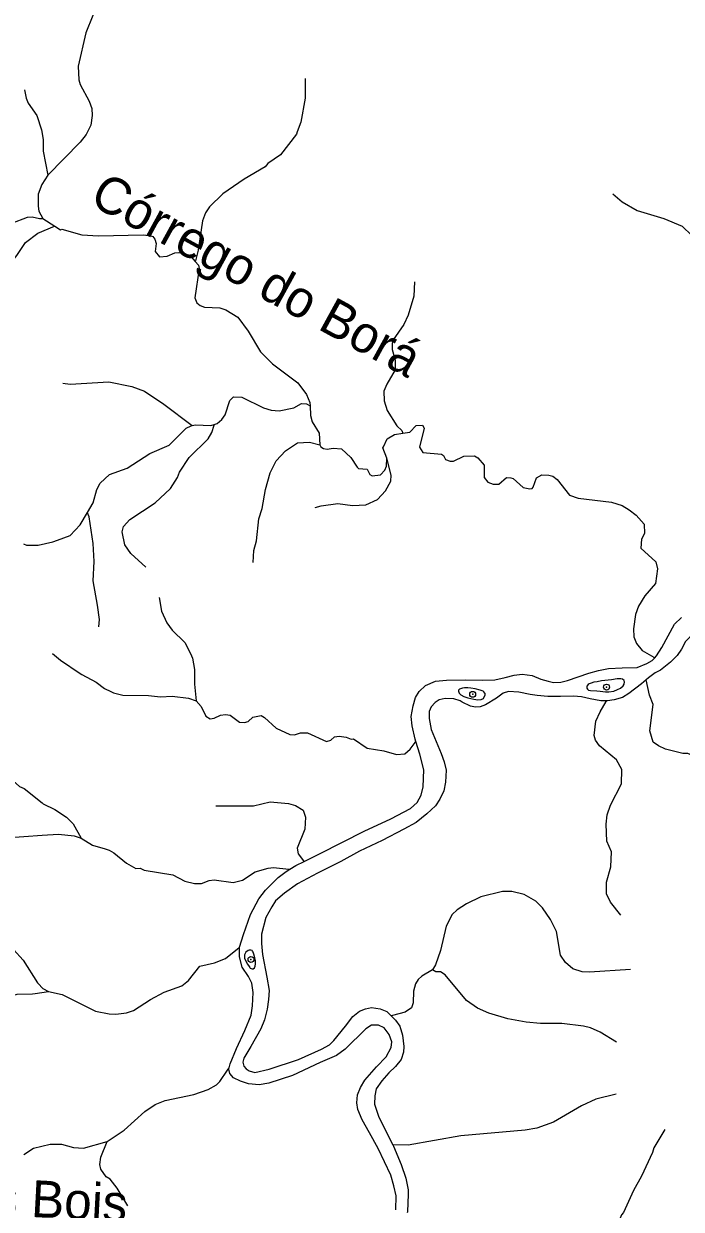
# Model space of a CAD drawing. Extents: x 393 to 446.6, y 8175.5 to 8231.
# Drawn here: x 402.2 to 405.77, y 8215.62 to 8222.05 of the extents above; entities that cross this region are included whole.
import ezdxf
from ezdxf.enums import TextEntityAlignment as Align

# ---------------------------------------------------------------- set-up
doc = ezdxf.new("R2010")
doc.units = 0
doc.header["$LTSCALE"] = 0.064
doc.header["$PDMODE"] = 32
doc.header["$PDSIZE"] = 0.032
doc.linetypes.add('LONG_DASHED', pattern=[7.5, 6, -1.5])
for name, color, linetype, lineweight in [('2', 7, 'Continuous', 25), ('7', 7, 'Continuous', 25), ('9', 7, 'LONG_DASHED', 25)]:
    doc.layers.add(name, color=color, linetype=linetype, lineweight=lineweight)
doc.layers.add('54', color=7, linetype='Continuous')
doc.layers.add('61', color=7, linetype='Continuous')

msp = doc.modelspace()

# ---------------------------------------------------------------- linework, layer by layer
at = {"layer": '2'}
for points in [[(406.6734, 8219.1519), (406.6511, 8219.1412), (406.5802, 8219.1176), (406.4922, 8219.0961), (406.3805, 8219.066), (406.2709, 8219.0252), (406.1979, 8218.9844), (406.142, 8218.9522), (406.1012, 8218.9135), (406.0132, 8218.8169), (405.9767, 8218.7846), (405.9358, 8218.7675), (405.895, 8218.7524), (405.8499, 8218.7417), (405.8156, 8218.7223), (405.7919, 8218.6987), (405.7705, 8218.6579), (405.7468, 8218.6235), (405.7103, 8218.587), (405.6566, 8218.5441), (405.6265, 8218.529), (405.59, 8218.5011), (405.5782, 8218.4907)], [(405.6244, 8218.6109), (405.6342, 8218.6216), (405.6635, 8218.6665), (405.7319, 8218.7934), (405.769, 8218.8285)], [(404.3299, 8218.1566), (404.3261, 8218.1686), (404.3105, 8218.2408), (404.3046, 8218.2916), (404.3144, 8218.3502), (404.3281, 8218.3951), (404.3476, 8218.4283), (404.3827, 8218.4595), (404.4354, 8218.483), (404.496, 8218.4888), (404.5994, 8218.4908), (404.6932, 8218.4888), (404.7576, 8218.4908), (404.8142, 8218.5044), (404.863, 8218.5161), (404.906, 8218.522), (404.9606, 8218.5142), (405.0075, 8218.4947), (405.0466, 8218.483), (405.0758, 8218.4771), (405.1149, 8218.479), (405.152, 8218.4869), (405.2672, 8218.5279), (405.3199, 8218.5415), (405.3746, 8218.5532), (405.4488, 8218.5552), (405.5288, 8218.5571), (405.5815, 8218.5786), (405.6108, 8218.5962), (405.6244, 8218.6109)], [(405.5782, 8218.4907), (405.5535, 8218.4689), (405.4848, 8218.4173), (405.4504, 8218.3959), (405.4053, 8218.383), (405.3688, 8218.3765), (405.3645, 8218.3765)], [(405.3645, 8218.3765), (405.3323, 8218.3765), (405.2743, 8218.3873), (405.227, 8218.398), (405.1841, 8218.4023), (405.1132, 8218.4002), (405.0445, 8218.4002), (404.9865, 8218.4066), (404.9499, 8218.4109), (404.8877, 8218.4238), (404.8318, 8218.4281), (404.8039, 8218.4195), (404.7674, 8218.3916), (404.7072, 8218.3551), (404.6793, 8218.3443), (404.6535, 8218.3422), (404.6256, 8218.3486), (404.5805, 8218.3701), (404.5698, 8218.3765), (404.5354, 8218.3873), (404.4881, 8218.3894), (404.4559, 8218.383), (404.4344, 8218.3679), (404.413, 8218.3443), (404.4022, 8218.3185), (404.4022, 8218.282), (404.413, 8218.2219), (404.4667, 8218.0909), (404.4838, 8218.0458), (404.4946, 8218.0006), (404.4903, 8217.9362), (404.4817, 8217.889), (404.4602, 8217.8438), (404.4366, 8217.8073), (404.3893, 8217.7644), (404.3313, 8217.7171), (404.2648, 8217.6806), (404.1466, 8217.6205), (404.0242, 8217.5625), (403.9232, 8217.5066), (403.7965, 8217.4422), (403.6891, 8217.3842), (403.6182, 8217.3348), (403.5688, 8217.2918), (403.5495, 8217.2596), (403.5173, 8217.2016), (403.4936, 8217.1114), (403.4936, 8217.062), (403.4979, 8217.0019), (403.5216, 8216.8794), (403.5345, 8216.8064), (403.5302, 8216.757), (403.5237, 8216.7054), (403.5087, 8216.6474), (403.4894, 8216.598), (403.4357, 8216.5035), (403.397, 8216.4391), (403.3927, 8216.4176), (403.397, 8216.3961), (403.4099, 8216.3811), (403.4271, 8216.3704), (403.4571, 8216.3618), (403.5345, 8216.379), (403.6934, 8216.4327), (403.818, 8216.4885), (403.8609, 8216.5121), (403.8846, 8216.5358), (403.949, 8216.6131), (403.9877, 8216.6646), (404.0242, 8216.6947), (404.0564, 8216.7076), (404.0886, 8216.714), (404.1359, 8216.7076), (404.1724, 8216.6926), (404.1959, 8216.6691)], [(403.7243, 8217.5059), (403.8107, 8217.5497), (404.0489, 8217.6707), (404.1933, 8217.7371), (404.3007, 8217.7937), (404.3378, 8217.825), (404.3593, 8217.866), (404.3691, 8217.9109), (404.373, 8218.0026), (404.3515, 8218.0886), (404.3299, 8218.1566)], [(403.6463, 8217.4634), (403.6798, 8217.4833), (403.7243, 8217.5059)], [(403.3747, 8217.0409), (403.3948, 8217.1104), (403.4338, 8217.2178), (403.4787, 8217.3037), (403.5139, 8217.3505), (403.5842, 8217.4189), (403.6271, 8217.4521), (403.6463, 8217.4634)], [(403.3179, 8216.3861), (403.3225, 8216.4094), (403.3577, 8216.4915), (403.4026, 8216.5891), (403.4377, 8216.673), (403.4436, 8216.7238), (403.4475, 8216.796), (403.4416, 8216.8468), (403.4221, 8216.8819), (403.3889, 8216.9327), (403.3733, 8216.9893), (403.3733, 8217.0362), (403.3747, 8217.0409)], [(404.1959, 8216.6691), (404.2196, 8216.6453), (404.2433, 8216.6131), (404.2583, 8216.5637), (404.2648, 8216.5035), (404.2626, 8216.4713), (404.2497, 8216.4327), (404.2196, 8216.394), (404.1831, 8216.3596), (404.1445, 8216.3167), (404.1144, 8216.2737), (404.108, 8216.235), (404.1058, 8216.1899), (404.1294, 8216.1191), (404.2055, 8215.969)], [(404.2207, 8215.6168), (404.2226, 8215.6929), (404.2109, 8215.7476), (404.1933, 8215.8042), (404.125, 8215.9487), (404.0781, 8216.0346), (404.0391, 8216.1049), (404.0157, 8216.1615), (404.0098, 8216.1966), (404.0137, 8216.2396), (404.0293, 8216.2806), (404.0528, 8216.3196), (404.1172, 8216.3919), (404.168, 8216.4465), (404.1953, 8216.4973), (404.1992, 8216.5285), (404.1855, 8216.5676), (404.1582, 8216.6047), (404.1269, 8216.6184), (404.0899, 8216.6184), (404.0586, 8216.5988), (403.9473, 8216.4875), (403.9005, 8216.4544), (403.8107, 8216.4153), (403.6603, 8216.345), (403.5334, 8216.304), (403.4807, 8216.2943), (403.4221, 8216.3001), (403.3792, 8216.3138), (403.3421, 8216.3333), (403.3206, 8216.3567), (403.3167, 8216.3802), (403.3179, 8216.3861)], [(404.2055, 8215.969), (404.2089, 8215.9623), (404.2497, 8215.8635), (404.2755, 8215.7883), (404.2884, 8215.726), (404.2884, 8215.7024), (404.2841, 8215.6057), (404.2836, 8215.6014)]]:
    msp.add_lwpolyline(points, dxfattribs=at)
for points in [[(405.2565, 8218.4569), (405.2559, 8218.4466), (405.2596, 8218.4411), (405.2656, 8218.435), (405.276, 8218.4326), (405.31, 8218.4308), (405.3288, 8218.4289), (405.3586, 8218.4253), (405.3762, 8218.4253), (405.4024, 8218.4302), (405.423, 8218.4387), (405.4388, 8218.4466), (405.4534, 8218.4581), (405.4589, 8218.4666), (405.4601, 8218.4806), (405.4592, 8218.4836), (405.4583, 8218.4867), (405.4504, 8218.4952), (405.4401, 8218.497), (405.4212, 8218.4964), (405.3908, 8218.4909), (405.3367, 8218.4848), (405.3118, 8218.4806), (405.2948, 8218.4776), (405.2802, 8218.4733), (405.2699, 8218.469), (405.2632, 8218.4648)], [(404.5614, 8218.4355), (404.5603, 8218.4297), (404.5646, 8218.4192), (404.5745, 8218.4102), (404.5898, 8218.4013), (404.6108, 8218.3934), (404.6276, 8218.3892), (404.6434, 8218.3855), (404.666, 8218.3829), (404.6844, 8218.3834), (404.697, 8218.3903), (404.7054, 8218.4087), (404.7049, 8218.4171), (404.7038, 8218.4192), (404.6991, 8218.425), (404.6938, 8218.4286), (404.6786, 8218.4344), (404.6518, 8218.4418), (404.6287, 8218.446), (404.6113, 8218.447), (404.5929, 8218.4475), (404.5819, 8218.4454), (404.5714, 8218.4428), (404.5656, 8218.4395)], [(403.4176, 8216.9487), (403.4255, 8216.9365), (403.4291, 8216.9316), (403.4322, 8216.928), (403.4376, 8216.925), (403.4419, 8216.9237), (403.448, 8216.9237), (403.4553, 8216.9286), (403.4595, 8216.9383), (403.4607, 8216.9517), (403.4601, 8216.9693), (403.4586, 8216.9766), (403.4571, 8216.9839), (403.4516, 8217.004), (403.4474, 8217.0149), (403.4446, 8217.0188), (403.4419, 8217.0228), (403.4358, 8217.0258), (403.4267, 8217.0258), (403.42, 8217.0228), (403.4085, 8217.0143), (403.4018, 8217.0003), (403.4012, 8216.9918), (403.4018, 8216.979)]]:
    msp.add_lwpolyline(points, close=True, dxfattribs=at)
at = {"layer": '54'}
for p in [(405.3637, 8218.4516), (404.6378, 8218.4123), (403.4361, 8216.9747)]:
    msp.add_point(p, dxfattribs=at)
at = {"layer": '7'}
msp.add_line((402.3076, 8220.9933), (402.3736, 8220.9511), dxfattribs=at)
for points in [[(402.5536, 8222.5668), (402.5414, 8222.4874), (402.543, 8222.4486), (402.5527, 8222.4228), (402.6237, 8222.3259), (402.635, 8222.3001), (402.6363, 8222.2694), (402.6366, 8222.2613), (402.6221, 8222.2097), (402.593, 8222.1563), (402.5785, 8222.0934), (402.5414, 8221.9997), (402.4994, 8221.8189), (402.5026, 8221.7446), (402.5107, 8221.7188), (402.5591, 8221.6283), (402.5737, 8221.5896), (402.5753, 8221.5508), (402.5672, 8221.4991), (402.543, 8221.4475), (402.5107, 8221.4071), (402.3357, 8221.2284)], [(403.7296, 8221.7521), (403.7299, 8221.6445), (403.7056, 8221.5153), (403.6869, 8221.4618), (403.683, 8221.4507), (403.5958, 8221.3376), (403.528, 8221.2908), (403.5135, 8221.273), (403.3988, 8221.2052), (403.2842, 8221.1261), (403.2115, 8221.0551), (403.1889, 8221.0228), (403.1727, 8220.9808), (403.1495, 8220.8205), (403.1351, 8220.763), (403.1342, 8220.7594)], [(402.209, 8221.6909), (402.2172, 8221.6444), (402.2281, 8221.6186), (402.2749, 8221.5508), (402.3007, 8221.4733), (402.3088, 8221.4216), (402.3088, 8221.357), (402.3357, 8221.2284)], [(402.3357, 8221.2284), (402.3031, 8221.1772), (402.283, 8221.1245), (402.283, 8221.0599), (402.2862, 8221.0324), (402.3076, 8220.9933)], [(405.3971, 8221.1271), (405.448, 8221.0825), (405.5288, 8221.0357), (405.6741, 8220.9921), (405.7742, 8220.9501), (405.8775, 8220.85), (406.0213, 8220.6142), (406.0713, 8220.5464), (406.1133, 8220.5012), (406.1941, 8220.4317), (406.2619, 8220.3881), (406.3426, 8220.3477), (406.4395, 8220.309), (406.475, 8220.3009), (406.5461, 8220.309), (406.6591, 8220.3445), (406.7108, 8220.3542), (406.7754, 8220.3607), (406.8755, 8220.3607), (406.9466, 8220.3704), (407.0047, 8220.3833), (407.0693, 8220.4107), (407.0979, 8220.4326)], [(402.14, 8220.9681), (402.2249, 8221.0001), (402.2507, 8221.0018), (402.2895, 8220.9921), (402.3076, 8220.9933)], [(402.0191, 8220.6416), (402.0413, 8220.6497), (402.0747, 8220.6772), (402.1471, 8220.7674), (402.1667, 8220.7918), (402.2135, 8220.8629), (402.2798, 8220.9129), (402.3716, 8220.9503), (402.3736, 8220.9511)], [(402.3736, 8220.9511), (402.4042, 8220.9316), (402.4106, 8220.9355), (402.5188, 8220.9049), (402.6092, 8220.8984), (402.8514, 8220.9049), (402.8934, 8220.8984), (402.9047, 8220.8952), (402.9144, 8220.8806), (402.9224, 8220.8565), (402.9176, 8220.8128), (402.9402, 8220.7854), (402.9822, 8220.7886), (403.0242, 8220.8064), (403.0452, 8220.808), (403.0791, 8220.8032), (403.113, 8220.7822), (403.1342, 8220.7594)], [(403.1342, 8220.7594), (403.1525, 8220.7397), (403.1549, 8220.7211), (403.1324, 8220.5626), (403.1421, 8220.5351), (403.1598, 8220.5205), (403.1841, 8220.5125), (403.2681, 8220.5076), (403.3003, 8220.4979), (403.3649, 8220.4576), (403.4214, 8220.3817), (403.4876, 8220.2702), (403.5522, 8220.2041), (403.6895, 8220.1007), (403.7379, 8220.0377), (403.7557, 8219.9957), (403.7563, 8219.9767)], [(404.3232, 8220.6497), (404.3193, 8220.5722), (404.2886, 8220.4689), (404.2643, 8220.4172), (404.2062, 8220.3349), (404.2014, 8220.3139), (404.2014, 8220.2816), (404.2175, 8220.2235), (404.2175, 8220.1718), (404.1723, 8220.0943), (404.1562, 8220.0555), (404.1578, 8220.0038), (404.1739, 8219.9522), (404.2272, 8219.8682), (404.253, 8219.8423), (404.2586, 8219.8283)], [(403.7563, 8219.9767), (403.7581, 8219.9241), (403.767, 8219.8908), (403.8057, 8219.8294), (403.8085, 8219.7658)], [(404.2586, 8219.8283), (404.2967, 8219.8343), (404.3322, 8219.8698), (404.3661, 8219.8714), (404.3741, 8219.8553), (404.3499, 8219.7519), (404.3677, 8219.7244), (404.4695, 8219.7148), (404.4791, 8219.7083), (404.4904, 8219.6857), (404.5163, 8219.676), (404.5341, 8219.676), (404.589, 8219.7034), (404.6471, 8219.7051), (404.6665, 8219.6954), (404.7004, 8219.655), (404.7004, 8219.5872), (404.7197, 8219.563), (404.7488, 8219.5517), (404.7795, 8219.5517), (404.8215, 8219.5872), (404.8441, 8219.5856), (404.857, 8219.5824), (404.9119, 8219.5339), (404.9474, 8219.5275), (404.9603, 8219.5291), (404.9652, 8219.5355), (404.9846, 8219.5856), (405.012, 8219.6017), (405.0508, 8219.6001), (405.0718, 8219.5953), (405.096, 8219.5775), (405.1622, 8219.4919), (405.209, 8219.4758), (405.3899, 8219.4548), (405.448, 8219.437), (405.4868, 8219.4128), (405.5239, 8219.3837), (405.5675, 8219.3353), (405.5691, 8219.2836), (405.553, 8219.2546), (405.5497, 8219.2045), (405.6305, 8219.1302), (405.6402, 8219.0931), (405.6288, 8219.014), (405.5707, 8218.9461), (405.5368, 8218.8912), (405.5207, 8218.8444), (405.5093, 8218.7669), (405.511, 8218.7249), (405.5255, 8218.6878), (405.5562, 8218.6506), (405.62, 8218.6135), (405.6244, 8218.6109)], [(404.1721, 8219.6924), (404.1513, 8219.7487), (404.154, 8219.7545), (404.1739, 8219.7971), (404.2143, 8219.8213), (404.2586, 8219.8283)], [(403.4477, 8219.1277), (403.4524, 8219.1917), (403.4666, 8219.2449), (403.4795, 8219.3644), (403.4973, 8219.4193), (403.5151, 8219.5226), (403.5409, 8219.6131), (403.5732, 8219.6777), (403.6233, 8219.7325), (403.6879, 8219.7761), (403.7525, 8219.7793), (403.8085, 8219.7658)], [(403.8085, 8219.7658), (403.8143, 8219.7541), (403.8295, 8219.7448), (403.8493, 8219.7425), (403.8817, 8219.7471), (403.9268, 8219.7438), (403.9769, 8219.697), (404.0108, 8219.6437), (404.0189, 8219.6373), (404.0657, 8219.6324), (404.0803, 8219.6049), (404.0932, 8219.5969), (404.1384, 8219.6034), (404.1616, 8219.6273), (404.1698, 8219.6494), (404.1721, 8219.6924)], [(403.7846, 8219.4247), (403.8172, 8219.4352), (403.9075, 8219.4467), (403.9866, 8219.437), (404.0593, 8219.4402), (404.1223, 8219.4693), (404.1658, 8219.5161), (404.1933, 8219.5678), (404.1965, 8219.6001), (404.1721, 8219.6924)], [(402.9391, 8218.9368), (402.9515, 8218.8638), (402.9806, 8218.7992), (403.008, 8218.7605), (403.0775, 8218.6926), (403.1074, 8218.6329), (403.1195, 8218.6087), (403.1292, 8218.5473), (403.1292, 8218.4666), (403.1383, 8218.377)], [(402.3609, 8218.6333), (402.4041, 8218.5973), (402.5109, 8218.5251), (402.5188, 8218.5198), (402.5963, 8218.4778), (402.6415, 8218.4439), (402.677, 8218.4273), (402.69, 8218.4213), (402.7416, 8218.4084), (402.8805, 8218.4068), (402.9451, 8218.3987), (403.0097, 8218.4019), (403.0969, 8218.3922), (403.1383, 8218.377)], [(406.1858, 8217.6868), (406.0869, 8217.8008), (405.9583, 8217.9821), (405.8953, 8218.0451), (405.8646, 8218.0661), (405.8049, 8218.0919), (405.7774, 8218.0919), (405.6838, 8218.1145), (405.645, 8218.1323), (405.616, 8218.1533), (405.5982, 8218.2146), (405.6159, 8218.3568), (405.5966, 8218.4084), (405.5782, 8218.4907)], [(403.1383, 8218.377), (403.1663, 8218.347), (403.1921, 8218.2938), (403.2148, 8218.2792), (403.2357, 8218.2824), (403.2713, 8218.3002), (403.2971, 8218.3034), (403.323, 8218.2986), (403.3746, 8218.2614), (403.4005, 8218.2598), (403.4214, 8218.2647), (403.4457, 8218.2889), (403.4909, 8218.297), (403.5102, 8218.2873), (403.5732, 8218.2292), (403.6459, 8218.1936), (403.6718, 8218.192), (403.704, 8218.2033), (403.7428, 8218.2033), (403.8462, 8218.1565), (403.8688, 8218.1645), (403.8897, 8218.1823), (403.914, 8218.1856), (403.9527, 8218.1807), (403.9786, 8218.1694), (403.9915, 8218.171), (404.0657, 8218.121), (404.1562, 8218.1064), (404.224, 8218.0854), (404.2692, 8218.0903), (404.2983, 8218.1145), (404.3264, 8218.1519), (404.3299, 8218.1566)], [(405.4417, 8217.2156), (405.385, 8217.2861), (405.3624, 8217.3313), (405.3624, 8217.3943), (405.3872, 8217.4762), (405.3899, 8217.5574), (405.3657, 8217.6155), (405.3608, 8217.7076), (405.3673, 8217.7593), (405.385, 8217.811), (405.4448, 8217.9272), (405.4464, 8218.0047), (405.4173, 8218.0564), (405.3253, 8218.1323), (405.3043, 8218.163), (405.2962, 8218.1888), (405.3059, 8218.2663), (405.3285, 8218.318), (405.3621, 8218.3727), (405.3645, 8218.3765)], [(401.9763, 8218.1182), (402.023, 8218.0774), (402.1118, 8217.974), (402.1813, 8217.9127), (402.2071, 8217.9013), (402.3034, 8217.8247), (402.3105, 8217.819), (402.3735, 8217.7883), (402.4364, 8217.7463), (402.4719, 8217.7108), (402.5157, 8217.6327)], [(403.245, 8217.8085), (403.4489, 8217.8077), (403.5393, 8217.8287), (403.6395, 8217.8206), (403.6782, 8217.8093), (403.7186, 8217.7835), (403.7315, 8217.7464), (403.7282, 8217.6818), (403.6862, 8217.5784), (403.6911, 8217.5477), (403.7216, 8217.5093), (403.7243, 8217.5059)], [(401.5068, 8217.2606), (401.5386, 8217.3023), (401.6016, 8217.3636), (401.7695, 8217.4799), (401.8357, 8217.5429), (401.868, 8217.5574), (401.9827, 8217.5832), (402.0602, 8217.6236), (402.1054, 8217.6349), (402.3037, 8217.6483), (402.3928, 8217.6543), (402.4768, 8217.6446), (402.5157, 8217.6327)], [(402.5157, 8217.6327), (402.5769, 8217.5945), (402.6453, 8217.5738), (402.6674, 8217.5671), (402.6932, 8217.5526), (402.761, 8217.496), (402.8127, 8217.4686), (402.8353, 8217.4702), (402.8579, 8217.4589), (403.0129, 8217.4331), (403.0775, 8217.3991), (403.1292, 8217.3862), (403.1679, 8217.3862), (403.2099, 8217.4024), (403.2358, 8217.4056), (403.3391, 8217.3927), (403.3908, 8217.404), (403.4586, 8217.4492), (403.5297, 8217.4702), (403.5587, 8217.4734), (403.6406, 8217.4641), (403.6463, 8217.4634)], [(405.4936, 8216.9204), (405.2704, 8216.905), (405.2316, 8216.9083), (405.18, 8216.9244), (405.1412, 8216.9583), (405.1137, 8216.9971), (405.0927, 8217.1263), (405.0604, 8217.1909), (405.0168, 8217.2538), (404.9797, 8217.291), (404.9167, 8217.3265), (404.8506, 8217.3426), (404.7989, 8217.3426), (404.6826, 8217.3136), (404.6051, 8217.2764), (404.5534, 8217.2441), (404.5259, 8217.2183), (404.4936, 8217.1553), (404.463, 8217.0229), (404.4355, 8216.9454), (404.4195, 8216.9191)], [(401.4404, 8216.9797), (401.5693, 8217.0068), (401.6468, 8217.0132), (401.692, 8217.0326), (401.7243, 8217.0617), (401.7598, 8217.0729), (401.8018, 8217.0762), (401.8535, 8217.0891), (401.9698, 8217.0891), (402.0085, 8217.0826), (402.0731, 8217.0665), (402.149, 8217.0294), (402.2006, 8216.9713), (402.2781, 8216.8485), (402.2826, 8216.8438), (402.3072, 8216.8178), (402.339, 8216.801)], [(402.339, 8216.801), (402.4123, 8216.7847), (402.5931, 8216.6935), (402.6674, 8216.6789), (402.7029, 8216.6773), (402.761, 8216.6854), (402.7998, 8216.6983), (402.8918, 8216.7581), (402.9661, 8216.7968), (403.0614, 8216.8307), (403.0969, 8216.8598), (403.1582, 8216.9389), (403.239, 8216.9567), (403.2971, 8216.9793), (403.3725, 8217.0392), (403.3747, 8217.0409)], [(404.4195, 8216.9191), (404.3613, 8216.884), (404.3418, 8216.8663), (404.3273, 8216.8421), (404.3176, 8216.8033), (404.316, 8216.7387), (404.3063, 8216.7129), (404.2725, 8216.6886), (404.2031, 8216.6709), (404.1959, 8216.6691)], [(405.4174, 8216.5266), (405.3285, 8216.5804), (405.2769, 8216.6031), (405.2381, 8216.6127), (405.1218, 8216.6273), (405.0056, 8216.6273), (404.9281, 8216.6354), (404.8279, 8216.6531), (404.7246, 8216.6838), (404.6632, 8216.7096), (404.6035, 8216.7516), (404.4888, 8216.8921), (404.463, 8216.9066), (404.4372, 8216.9082), (404.4195, 8216.9191)], [(402.1259, 8216.7673), (402.1504, 8216.7801), (402.1678, 8216.7859), (402.2516, 8216.7888), (402.2666, 8216.7909), (402.339, 8216.801)], [(402.6568, 8215.988), (402.7481, 8216.0492), (402.8611, 8216.1493), (402.9176, 8216.188), (402.9709, 8216.2106), (403.126, 8216.2429), (403.2035, 8216.2688), (403.2487, 8216.2946), (403.2681, 8216.3124), (403.3095, 8216.3737), (403.3179, 8216.3861)], [(405.4147, 8216.244), (405.3059, 8216.2171), (405.2284, 8216.18), (405.0766, 8216.0928), (404.9862, 8216.0605), (404.9216, 8216.0492), (404.5728, 8216.0185), (404.2886, 8215.9668), (404.2055, 8215.969)], [(405.6798, 8216.0526), (405.6192, 8215.9539), (405.6127, 8215.9281), (405.553, 8215.7989), (405.5094, 8215.7214), (405.4561, 8215.6019), (405.4448, 8215.589), (405.4012, 8215.4808), (405.3656, 8215.434), (405.3124, 8215.3871), (405.2542, 8215.3564), (405.1477, 8215.3306), (404.9746, 8215.3209)], [(402.2057, 8215.9164), (402.2572, 8215.9507), (402.3476, 8215.9733), (402.409, 8215.9733), (402.4736, 8215.9555), (402.5284, 8215.9507), (402.6568, 8215.988)], [(402.7692, 8215.6383), (402.7109, 8215.7343), (402.6722, 8215.7828), (402.6512, 8215.7956), (402.6221, 8215.8377), (402.6172, 8215.8635), (402.6221, 8215.9023), (402.6568, 8215.988)]]:
    msp.add_lwpolyline(points, dxfattribs=at)
at = {"layer": '9'}
for points in [[(402.4166, 8220.1002), (402.4551, 8220.0944), (402.6658, 8220.1067), (402.7901, 8220.0813), (402.8595, 8220.0555), (402.9645, 8219.986), (403.118, 8219.87)], [(403.2374, 8219.8761), (403.252, 8219.8809), (403.2776, 8219.9019), (403.2963, 8219.9288), (403.322, 8220.0058), (403.3418, 8220.0256), (403.3874, 8220.0232), (403.5038, 8219.9667), (403.5458, 8219.9537), (403.5894, 8219.9489), (403.6685, 8219.9667), (403.7105, 8219.9893), (403.7378, 8219.9868), (403.7563, 8219.9767)], [(402.5496, 8219.3977), (402.5813, 8219.4507), (402.6011, 8219.523), (402.618, 8219.5574), (402.669, 8219.605), (402.7642, 8219.6389), (402.887, 8219.718), (402.9919, 8219.7632), (403.0839, 8219.8553), (403.1113, 8219.8687), (403.118, 8219.87)], [(402.8658, 8219.101), (402.7852, 8219.1754), (402.7531, 8219.2226), (402.7384, 8219.2933), (402.7448, 8219.3224), (402.7788, 8219.3595), (402.916, 8219.4499), (403, 8219.5291), (403.0371, 8219.5872), (403.0484, 8219.6179), (403.1017, 8219.697), (403.2034, 8219.7971), (403.2244, 8219.8327), (403.2362, 8219.8722), (403.2374, 8219.8761)], [(403.118, 8219.87), (403.1358, 8219.8734), (403.2187, 8219.8699), (403.2374, 8219.8761)], [(402.2027, 8219.2289), (402.2185, 8219.2217), (402.2827, 8219.2205), (402.3622, 8219.2384), (402.3869, 8219.2478), (402.4558, 8219.274), (402.5101, 8219.3317), (402.5496, 8219.3977)], [(402.612, 8218.7781), (402.6143, 8218.8178), (402.6044, 8218.8961), (402.5801, 8219.0285), (402.5866, 8219.1319), (402.5802, 8219.2303), (402.5591, 8219.3757), (402.5498, 8219.3971), (402.5496, 8219.3977)]]:
    msp.add_lwpolyline(points, dxfattribs=at)

# ---------------------------------------------------------------- texts
at = {"layer": '61'}
for s, rotation, p in [('Córrego do Borá', 331.294, (403.4199, 8220.6002)), ('Córrego dos Bois', 357.031, (401.7292, 8215.6051))]:
    msp.add_text(s, height=0.2, rotation=rotation, dxfattribs=at).set_placement(p, align=Align.CENTER)

doc.saveas('drawing.dxf')
